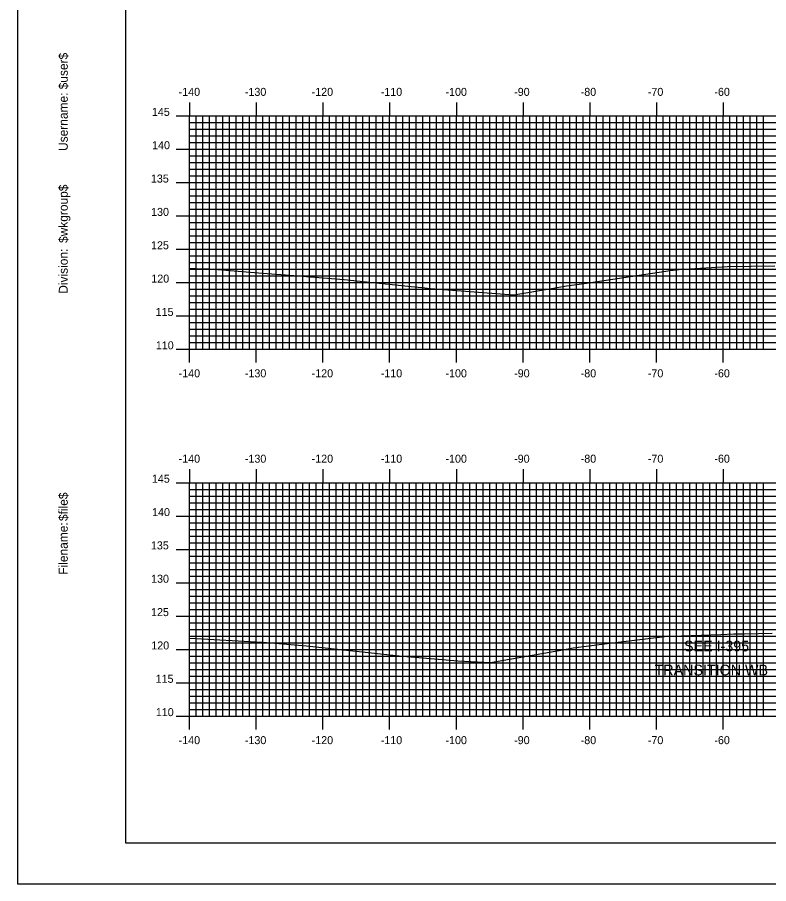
# Model space of a CAD drawing. Extents: x 853328 to 853671, y 364661 to 364881.
# Drawn here: x 853327.5 to 853440.1, y 364661.3 to 364791.1 of the extents above; entities that cross this region are included whole.
import ezdxf

# ---------------------------------------------------------------- set-up
doc = ezdxf.new("R2010")
doc.units = 0
for name, color, linetype in [('ANNOTATION', 7, 'Continuous'), ('BORDER', 7, 'Continuous'), ('H_V ANNOTATION', 7, 'Continuous'), ('MAJOR', 7, 'Continuous'), ('MINOR', 7, 'Continuous'), ('PLOT BOUNDARY', 7, 'Continuous'), ('S_Roadway_Centerline', 7, 'Continuous')]:
    doc.layers.add(name, color=color, linetype=linetype)

msp = doc.modelspace()

# ---------------------------------------------------------------- linework, layer by layer
at = {"layer": 'BORDER'}
msp.add_lwpolyline([(853343.69, 364667.37), (853663.69, 364667.37), (853663.69, 364877.37), (853343.69, 364877.37)], close=True, dxfattribs=at)
at = {"layer": 'MAJOR'}
for p, q in [((853353.29, 364778.38), (853353.29, 364776.37)), ((853363.29, 364778.38), (853363.29, 364776.37)), ((853373.29, 364778.38), (853373.29, 364776.37)), ((853383.29, 364778.38), (853383.29, 364776.37)), ((853393.29, 364778.38), (853393.29, 364776.37)), ((853403.29, 364778.38), (853403.29, 364776.37)), ((853413.29, 364778.38), (853413.29, 364776.37)), ((853423.29, 364778.38), (853423.29, 364776.37)), ((853433.29, 364778.38), (853433.29, 364776.37)), ((853351.29, 364776.37), (853353.29, 364776.37)), ((853353.29, 364776.37), (853633.29, 364776.37)), ((853353.29, 364741.37), (853353.29, 364776.37)), ((853353.29, 364741.37), (853353.29, 364776.37)), ((853353.29, 364776.37), (853633.29, 364776.37)), ((853363.29, 364741.37), (853363.29, 364776.37)), ((853373.29, 364741.37), (853373.29, 364776.37)), ((853383.29, 364741.37), (853383.29, 364776.37)), ((853393.29, 364741.37), (853393.29, 364776.37)), ((853403.29, 364741.37), (853403.29, 364776.37)), ((853413.29, 364741.37), (853413.29, 364776.37)), ((853423.29, 364741.37), (853423.29, 364776.37)), ((853433.29, 364741.37), (853433.29, 364776.37)), ((853351.29, 364771.37), (853353.29, 364771.37)), ((853353.29, 364771.37), (853633.29, 364771.37)), ((853351.29, 364766.37), (853353.29, 364766.37)), ((853353.29, 364766.37), (853633.29, 364766.37)), ((853351.29, 364761.37), (853353.29, 364761.37)), ((853353.29, 364761.37), (853633.29, 364761.37)), ((853351.29, 364756.37), (853353.29, 364756.37)), ((853353.29, 364756.37), (853633.29, 364756.37)), ((853351.29, 364751.37), (853353.29, 364751.37)), ((853353.29, 364751.37), (853633.29, 364751.37)), ((853351.29, 364746.37), (853353.29, 364746.37)), ((853353.29, 364746.37), (853633.29, 364746.37)), ((853351.29, 364741.37), (853353.29, 364741.37)), ((853353.29, 364741.37), (853633.29, 364741.37)), ((853353.29, 364741.37), (853633.29, 364741.37)), ((853353.29, 364739.37), (853353.29, 364741.37)), ((853363.29, 364739.37), (853363.29, 364741.37)), ((853373.29, 364739.37), (853373.29, 364741.37)), ((853383.29, 364739.37), (853383.29, 364741.37)), ((853393.29, 364739.37), (853393.29, 364741.37)), ((853403.29, 364739.37), (853403.29, 364741.37)), ((853413.29, 364739.37), (853413.29, 364741.37)), ((853423.29, 364739.37), (853423.29, 364741.37)), ((853433.29, 364739.37), (853433.29, 364741.37)), ((853353.29, 364723.38), (853353.29, 364721.37)), ((853363.29, 364723.38), (853363.29, 364721.37)), ((853373.29, 364723.38), (853373.29, 364721.37)), ((853383.29, 364723.38), (853383.29, 364721.37)), ((853393.29, 364723.38), (853393.29, 364721.37)), ((853403.29, 364723.38), (853403.29, 364721.37)), ((853413.29, 364723.38), (853413.29, 364721.37)), ((853423.29, 364723.38), (853423.29, 364721.37)), ((853433.29, 364723.38), (853433.29, 364721.37)), ((853351.29, 364721.37), (853353.29, 364721.37)), ((853353.29, 364721.37), (853633.29, 364721.37)), ((853353.29, 364686.37), (853353.29, 364721.37)), ((853353.29, 364686.37), (853353.29, 364721.37)), ((853353.29, 364721.37), (853633.29, 364721.37)), ((853363.29, 364686.37), (853363.29, 364721.37)), ((853373.29, 364686.37), (853373.29, 364721.37)), ((853383.29, 364686.37), (853383.29, 364721.37)), ((853393.29, 364686.37), (853393.29, 364721.37)), ((853403.29, 364686.37), (853403.29, 364721.37)), ((853413.29, 364686.37), (853413.29, 364721.37)), ((853423.29, 364686.37), (853423.29, 364721.37)), ((853433.29, 364686.37), (853433.29, 364721.37)), ((853351.29, 364716.37), (853353.29, 364716.37)), ((853353.29, 364716.37), (853633.29, 364716.37)), ((853351.29, 364711.37), (853353.29, 364711.37)), ((853353.29, 364711.37), (853633.29, 364711.37)), ((853351.29, 364706.37), (853353.29, 364706.37)), ((853353.29, 364706.37), (853633.29, 364706.37)), ((853351.29, 364701.37), (853353.29, 364701.37)), ((853353.29, 364701.37), (853633.29, 364701.37)), ((853351.29, 364696.37), (853353.29, 364696.37)), ((853353.29, 364696.37), (853633.29, 364696.37)), ((853351.29, 364691.37), (853353.29, 364691.37)), ((853353.29, 364691.37), (853633.29, 364691.37)), ((853351.29, 364686.37), (853353.29, 364686.37)), ((853353.29, 364686.37), (853633.29, 364686.37)), ((853353.29, 364686.37), (853633.29, 364686.37)), ((853353.29, 364684.37), (853353.29, 364686.37)), ((853363.29, 364684.37), (853363.29, 364686.37)), ((853373.29, 364684.37), (853373.29, 364686.37)), ((853383.29, 364684.37), (853383.29, 364686.37)), ((853393.29, 364684.37), (853393.29, 364686.37)), ((853403.29, 364684.37), (853403.29, 364686.37)), ((853413.29, 364684.37), (853413.29, 364686.37)), ((853423.29, 364684.37), (853423.29, 364686.37)), ((853433.29, 364684.37), (853433.29, 364686.37))]:
    msp.add_line(p, q, dxfattribs=at)
at = {"layer": 'MINOR'}
for p, q in [((853354.29, 364741.37), (853354.29, 364776.37)), ((853355.29, 364741.37), (853355.29, 364776.37)), ((853356.29, 364741.37), (853356.29, 364776.37)), ((853357.29, 364741.37), (853357.29, 364776.37)), ((853358.29, 364741.37), (853358.29, 364776.37)), ((853359.29, 364741.37), (853359.29, 364776.37)), ((853360.29, 364741.37), (853360.29, 364776.37)), ((853361.29, 364741.37), (853361.29, 364776.37)), ((853362.29, 364741.37), (853362.29, 364776.37)), ((853364.29, 364741.37), (853364.29, 364776.37)), ((853365.29, 364741.37), (853365.29, 364776.37)), ((853366.29, 364741.37), (853366.29, 364776.37)), ((853367.29, 364741.37), (853367.29, 364776.37)), ((853368.29, 364741.37), (853368.29, 364776.37)), ((853369.29, 364741.37), (853369.29, 364776.37)), ((853370.29, 364741.37), (853370.29, 364776.37)), ((853371.29, 364741.37), (853371.29, 364776.37)), ((853372.29, 364741.37), (853372.29, 364776.37)), ((853374.29, 364741.37), (853374.29, 364776.37)), ((853375.29, 364741.37), (853375.29, 364776.37)), ((853376.29, 364741.37), (853376.29, 364776.37)), ((853377.29, 364741.37), (853377.29, 364776.37)), ((853378.29, 364741.37), (853378.29, 364776.37)), ((853379.29, 364741.37), (853379.29, 364776.37)), ((853380.29, 364741.37), (853380.29, 364776.37)), ((853381.29, 364741.37), (853381.29, 364776.37)), ((853382.29, 364741.37), (853382.29, 364776.37)), ((853384.29, 364741.37), (853384.29, 364776.37)), ((853385.29, 364741.37), (853385.29, 364776.37)), ((853386.29, 364741.37), (853386.29, 364776.37)), ((853387.29, 364741.37), (853387.29, 364776.37)), ((853388.29, 364741.37), (853388.29, 364776.37)), ((853389.29, 364741.37), (853389.29, 364776.37)), ((853390.29, 364741.37), (853390.29, 364776.37)), ((853391.29, 364741.37), (853391.29, 364776.37)), ((853392.29, 364741.37), (853392.29, 364776.37)), ((853394.29, 364741.37), (853394.29, 364776.37)), ((853395.29, 364741.37), (853395.29, 364776.37)), ((853396.29, 364741.37), (853396.29, 364776.37)), ((853397.29, 364741.37), (853397.29, 364776.37)), ((853398.29, 364741.37), (853398.29, 364776.37)), ((853399.29, 364741.37), (853399.29, 364776.37)), ((853400.29, 364741.37), (853400.29, 364776.37)), ((853401.29, 364741.37), (853401.29, 364776.37)), ((853402.29, 364741.37), (853402.29, 364776.37)), ((853404.29, 364741.37), (853404.29, 364776.37)), ((853405.29, 364741.37), (853405.29, 364776.37)), ((853406.29, 364741.37), (853406.29, 364776.37)), ((853407.29, 364741.37), (853407.29, 364776.37)), ((853408.29, 364741.37), (853408.29, 364776.37)), ((853409.29, 364741.37), (853409.29, 364776.37)), ((853410.29, 364741.37), (853410.29, 364776.37)), ((853411.29, 364741.37), (853411.29, 364776.37)), ((853412.29, 364741.37), (853412.29, 364776.37)), ((853414.29, 364741.37), (853414.29, 364776.37)), ((853415.29, 364741.37), (853415.29, 364776.37)), ((853416.29, 364741.37), (853416.29, 364776.37)), ((853417.29, 364741.37), (853417.29, 364776.37)), ((853418.29, 364741.37), (853418.29, 364776.37)), ((853419.29, 364741.37), (853419.29, 364776.37)), ((853420.29, 364741.37), (853420.29, 364776.37)), ((853421.29, 364741.37), (853421.29, 364776.37)), ((853422.29, 364741.37), (853422.29, 364776.37)), ((853424.29, 364741.37), (853424.29, 364776.37)), ((853425.29, 364741.37), (853425.29, 364776.37)), ((853426.29, 364741.37), (853426.29, 364776.37)), ((853427.29, 364741.37), (853427.29, 364776.37)), ((853428.29, 364741.37), (853428.29, 364776.37)), ((853429.29, 364741.37), (853429.29, 364776.37)), ((853430.29, 364741.37), (853430.29, 364776.37)), ((853431.29, 364741.37), (853431.29, 364776.37)), ((853432.29, 364741.37), (853432.29, 364776.37)), ((853434.29, 364741.37), (853434.29, 364776.37)), ((853435.29, 364741.37), (853435.29, 364776.37)), ((853436.29, 364741.37), (853436.29, 364776.37)), ((853437.29, 364741.37), (853437.29, 364776.37)), ((853438.29, 364741.37), (853438.29, 364776.37)), ((853439.29, 364741.37), (853439.29, 364776.37)), ((853353.29, 364775.37), (853633.29, 364775.37)), ((853353.29, 364775.37), (853355.3, 364775.37)), ((853353.29, 364774.37), (853633.29, 364774.37)), ((853353.29, 364774.37), (853355.3, 364774.37)), ((853353.29, 364773.37), (853633.29, 364773.37)), ((853353.29, 364773.37), (853355.3, 364773.37)), ((853353.29, 364772.37), (853633.29, 364772.37)), ((853353.29, 364772.37), (853355.3, 364772.37)), ((853353.29, 364770.37), (853633.29, 364770.37)), ((853353.29, 364770.37), (853355.3, 364770.37)), ((853353.29, 364769.37), (853633.29, 364769.37)), ((853353.29, 364769.37), (853355.3, 364769.37)), ((853353.29, 364768.37), (853633.29, 364768.37)), ((853353.29, 364768.37), (853355.3, 364768.37)), ((853353.29, 364767.37), (853633.29, 364767.37)), ((853353.29, 364767.37), (853355.3, 364767.37)), ((853353.29, 364765.37), (853633.29, 364765.37)), ((853353.29, 364765.37), (853355.3, 364765.37)), ((853353.29, 364764.37), (853633.29, 364764.37)), ((853353.29, 364764.37), (853355.3, 364764.37)), ((853353.29, 364763.37), (853633.29, 364763.37)), ((853353.29, 364763.37), (853355.3, 364763.37)), ((853353.29, 364762.37), (853633.29, 364762.37)), ((853353.29, 364762.37), (853355.3, 364762.37)), ((853353.29, 364760.37), (853633.29, 364760.37)), ((853353.29, 364760.37), (853355.3, 364760.37)), ((853353.29, 364759.37), (853633.29, 364759.37)), ((853353.29, 364759.37), (853355.3, 364759.37)), ((853353.29, 364758.37), (853633.29, 364758.37)), ((853353.29, 364758.37), (853355.3, 364758.37)), ((853353.29, 364757.37), (853633.29, 364757.37)), ((853353.29, 364757.37), (853355.3, 364757.37)), ((853353.29, 364755.37), (853633.29, 364755.37)), ((853353.29, 364755.37), (853355.3, 364755.37)), ((853353.29, 364754.37), (853633.29, 364754.37)), ((853353.29, 364754.37), (853355.3, 364754.37)), ((853353.29, 364753.37), (853633.29, 364753.37)), ((853353.29, 364753.37), (853355.3, 364753.37)), ((853353.29, 364752.37), (853633.29, 364752.37)), ((853353.29, 364752.37), (853355.3, 364752.37)), ((853353.29, 364750.37), (853633.29, 364750.37)), ((853353.29, 364750.37), (853355.3, 364750.37)), ((853353.29, 364749.37), (853633.29, 364749.37)), ((853353.29, 364749.37), (853355.3, 364749.37)), ((853353.29, 364748.37), (853633.29, 364748.37)), ((853353.29, 364748.37), (853355.3, 364748.37)), ((853353.29, 364747.37), (853633.29, 364747.37)), ((853353.29, 364747.37), (853355.3, 364747.37)), ((853353.29, 364745.37), (853633.29, 364745.37)), ((853353.29, 364745.37), (853355.3, 364745.37)), ((853353.29, 364744.37), (853633.29, 364744.37)), ((853353.29, 364744.37), (853355.3, 364744.37)), ((853353.29, 364743.37), (853633.29, 364743.37)), ((853353.29, 364743.37), (853355.3, 364743.37)), ((853353.29, 364742.37), (853633.29, 364742.37)), ((853353.29, 364742.37), (853355.3, 364742.37)), ((853354.29, 364686.37), (853354.29, 364721.37)), ((853355.29, 364686.37), (853355.29, 364721.37)), ((853356.29, 364686.37), (853356.29, 364721.37)), ((853357.29, 364686.37), (853357.29, 364721.37)), ((853358.29, 364686.37), (853358.29, 364721.37)), ((853359.29, 364686.37), (853359.29, 364721.37)), ((853360.29, 364686.37), (853360.29, 364721.37)), ((853361.29, 364686.37), (853361.29, 364721.37)), ((853362.29, 364686.37), (853362.29, 364721.37)), ((853364.29, 364686.37), (853364.29, 364721.37)), ((853365.29, 364686.37), (853365.29, 364721.37)), ((853366.29, 364686.37), (853366.29, 364721.37)), ((853367.29, 364686.37), (853367.29, 364721.37)), ((853368.29, 364686.37), (853368.29, 364721.37)), ((853369.29, 364686.37), (853369.29, 364721.37)), ((853370.29, 364686.37), (853370.29, 364721.37)), ((853371.29, 364686.37), (853371.29, 364721.37)), ((853372.29, 364686.37), (853372.29, 364721.37)), ((853374.29, 364686.37), (853374.29, 364721.37)), ((853375.29, 364686.37), (853375.29, 364721.37)), ((853376.29, 364686.37), (853376.29, 364721.37)), ((853377.29, 364686.37), (853377.29, 364721.37)), ((853378.29, 364686.37), (853378.29, 364721.37)), ((853379.29, 364686.37), (853379.29, 364721.37)), ((853380.29, 364686.37), (853380.29, 364721.37)), ((853381.29, 364686.37), (853381.29, 364721.37)), ((853382.29, 364686.37), (853382.29, 364721.37)), ((853384.29, 364686.37), (853384.29, 364721.37)), ((853385.29, 364686.37), (853385.29, 364721.37)), ((853386.29, 364686.37), (853386.29, 364721.37)), ((853387.29, 364686.37), (853387.29, 364721.37)), ((853388.29, 364686.37), (853388.29, 364721.37)), ((853389.29, 364686.37), (853389.29, 364721.37)), ((853390.29, 364686.37), (853390.29, 364721.37)), ((853391.29, 364686.37), (853391.29, 364721.37)), ((853392.29, 364686.37), (853392.29, 364721.37)), ((853394.29, 364686.37), (853394.29, 364721.37)), ((853395.29, 364686.37), (853395.29, 364721.37)), ((853396.29, 364686.37), (853396.29, 364721.37)), ((853397.29, 364686.37), (853397.29, 364721.37)), ((853398.29, 364686.37), (853398.29, 364721.37)), ((853399.29, 364686.37), (853399.29, 364721.37)), ((853400.29, 364686.37), (853400.29, 364721.37)), ((853401.29, 364686.37), (853401.29, 364721.37)), ((853402.29, 364686.37), (853402.29, 364721.37)), ((853404.29, 364686.37), (853404.29, 364721.37)), ((853405.29, 364686.37), (853405.29, 364721.37)), ((853406.29, 364686.37), (853406.29, 364721.37)), ((853407.29, 364686.37), (853407.29, 364721.37)), ((853408.29, 364686.37), (853408.29, 364721.37)), ((853409.29, 364686.37), (853409.29, 364721.37)), ((853410.29, 364686.37), (853410.29, 364721.37)), ((853411.29, 364686.37), (853411.29, 364721.37)), ((853412.29, 364686.37), (853412.29, 364721.37)), ((853414.29, 364686.37), (853414.29, 364721.37)), ((853415.29, 364686.37), (853415.29, 364721.37)), ((853416.29, 364686.37), (853416.29, 364721.37)), ((853417.29, 364686.37), (853417.29, 364721.37)), ((853418.29, 364686.37), (853418.29, 364721.37)), ((853419.29, 364686.37), (853419.29, 364721.37)), ((853420.29, 364686.37), (853420.29, 364721.37)), ((853421.29, 364686.37), (853421.29, 364721.37)), ((853422.29, 364686.37), (853422.29, 364721.37)), ((853424.29, 364686.37), (853424.29, 364721.37)), ((853425.29, 364686.37), (853425.29, 364721.37)), ((853426.29, 364686.37), (853426.29, 364721.37)), ((853427.29, 364686.37), (853427.29, 364721.37)), ((853428.29, 364686.37), (853428.29, 364721.37)), ((853429.29, 364686.37), (853429.29, 364721.37)), ((853430.29, 364686.37), (853430.29, 364721.37)), ((853431.29, 364686.37), (853431.29, 364721.37)), ((853432.29, 364686.37), (853432.29, 364721.37)), ((853434.29, 364686.37), (853434.29, 364721.37)), ((853435.29, 364686.37), (853435.29, 364721.37)), ((853436.29, 364686.37), (853436.29, 364721.37)), ((853437.29, 364686.37), (853437.29, 364721.37)), ((853438.29, 364686.37), (853438.29, 364721.37)), ((853439.29, 364686.37), (853439.29, 364721.37)), ((853353.29, 364720.37), (853633.29, 364720.37)), ((853353.29, 364720.37), (853355.3, 364720.37)), ((853353.29, 364719.37), (853633.29, 364719.37)), ((853353.29, 364719.37), (853355.3, 364719.37)), ((853353.29, 364718.37), (853633.29, 364718.37)), ((853353.29, 364718.37), (853355.3, 364718.37)), ((853353.29, 364717.37), (853633.29, 364717.37)), ((853353.29, 364717.37), (853355.3, 364717.37)), ((853353.29, 364715.37), (853633.29, 364715.37)), ((853353.29, 364715.37), (853355.3, 364715.37)), ((853353.29, 364714.37), (853633.29, 364714.37)), ((853353.29, 364714.37), (853355.3, 364714.37)), ((853353.29, 364713.37), (853633.29, 364713.37)), ((853353.29, 364713.37), (853355.3, 364713.37)), ((853353.29, 364712.37), (853633.29, 364712.37)), ((853353.29, 364712.37), (853355.3, 364712.37)), ((853353.29, 364710.37), (853633.29, 364710.37)), ((853353.29, 364710.37), (853355.3, 364710.37)), ((853353.29, 364709.37), (853633.29, 364709.37)), ((853353.29, 364709.37), (853355.3, 364709.37)), ((853353.29, 364708.37), (853633.29, 364708.37)), ((853353.29, 364708.37), (853355.3, 364708.37)), ((853353.29, 364707.37), (853633.29, 364707.37)), ((853353.29, 364707.37), (853355.3, 364707.37)), ((853353.29, 364705.37), (853633.29, 364705.37)), ((853353.29, 364705.37), (853355.3, 364705.37)), ((853353.29, 364704.37), (853633.29, 364704.37)), ((853353.29, 364704.37), (853355.3, 364704.37)), ((853353.29, 364703.37), (853633.29, 364703.37)), ((853353.29, 364703.37), (853355.3, 364703.37)), ((853353.29, 364702.37), (853633.29, 364702.37)), ((853353.29, 364702.37), (853355.3, 364702.37)), ((853353.29, 364700.37), (853633.29, 364700.37)), ((853353.29, 364700.37), (853355.3, 364700.37)), ((853353.29, 364699.37), (853633.29, 364699.37)), ((853353.29, 364699.37), (853355.3, 364699.37)), ((853353.29, 364698.37), (853633.29, 364698.37)), ((853353.29, 364698.37), (853355.3, 364698.37)), ((853353.29, 364697.37), (853633.29, 364697.37)), ((853353.29, 364697.37), (853355.3, 364697.37)), ((853353.29, 364695.37), (853633.29, 364695.37)), ((853353.29, 364695.37), (853355.3, 364695.37)), ((853353.29, 364694.37), (853633.29, 364694.37)), ((853353.29, 364694.37), (853355.3, 364694.37)), ((853353.29, 364693.37), (853633.29, 364693.37)), ((853353.29, 364693.37), (853355.3, 364693.37)), ((853353.29, 364692.37), (853633.29, 364692.37)), ((853353.29, 364692.37), (853355.3, 364692.37)), ((853353.29, 364690.37), (853633.29, 364690.37)), ((853353.29, 364690.37), (853355.3, 364690.37)), ((853353.29, 364689.37), (853633.29, 364689.37)), ((853353.29, 364689.37), (853355.3, 364689.37)), ((853353.29, 364688.37), (853633.29, 364688.37)), ((853353.29, 364688.37), (853355.3, 364688.37)), ((853353.29, 364687.37), (853633.29, 364687.37)), ((853353.29, 364687.37), (853355.3, 364687.37))]:
    msp.add_line(p, q, dxfattribs=at)
at = {"layer": 'PLOT BOUNDARY'}
msp.add_lwpolyline([(853327.51, 364661.25), (853667.51, 364661.25), (853667.51, 364881.25), (853327.51, 364881.25)], close=True, dxfattribs=at)
at = {"layer": 'S_Roadway_Centerline'}
for points in [[(853353.29, 364753.52), (853354.2, 364753.5), (853356.18, 364753.45), (853356.94, 364753.4), (853364.24, 364752.77), (853367.04, 364752.57), (853376.48, 364751.83), (853386.51, 364750.8), (853388.12, 364750.63), (853389.39, 364750.5), (853401.2, 364749.59), (853401.88, 364749.56), (853407.56, 364750.51), (853409.8, 364750.89), (853410.53, 364750.99), (853412.42, 364751.25), (853425.32, 364753.2), (853427.12, 364753.4), (853427.35, 364753.41), (853431.54, 364753.65), (853433.91, 364753.78), (853441.02, 364753.88)], [(853353.29, 364698.08), (853364.25, 364697.46), (853366.07, 364697.31), (853370.85, 364696.89), (853384.71, 364695.43), (853393.52, 364694.67), (853398.39, 364694.4), (853398.4, 364694.39), (853409.22, 364696.33), (853410.81, 364696.59), (853415.49, 364697.22), (853422.42, 364698.05), (853424.49, 364698.3), (853425.53, 364698.35), (853432.91, 364698.6), (853434.86, 364698.7), (853436.47, 364698.72), (853440.63, 364698.82)]]:
    msp.add_lwpolyline(points, dxfattribs=at)

# ---------------------------------------------------------------- texts
at = {"layer": 'ANNOTATION'}
for s, p in [('SEE I-395 ', (853427.4, 364696.08)), ('TRANSITION WB', (853422.99, 364692.48))]:
    msp.add_text(s, height=1.6, dxfattribs=at).set_placement(p)
at = {"layer": 'BORDER'}
for s, p in [('$user$', (853335.06, 364780.35)), ('Username:', (853335.06, 364771.11)), ('$wkgroup$', (853335.06, 364757.31)), ('Division:', (853335.06, 364749.7)), ('$file$', (853335.06, 364715.62)), ('Filename:', (853335.06, 364707.57))]:
    msp.add_text(s, height=1.339, rotation=90, dxfattribs=at).set_placement(p)
at = {"layer": 'H_V ANNOTATION'}
for s, p in [('-140', (853351.68, 364779.37)), ('-130', (853361.6, 364779.37)), ('-120', (853371.61, 364779.37)), ('-110', (853381.96, 364779.37)), ('-100', (853391.66, 364779.37)), ('-90', (853401.95, 364779.37)), ('-80', (853411.92, 364779.37)), ('-70', (853421.98, 364779.37)), ('-60', (853431.95, 364779.37)), ('145', (853347.67, 364776.37)), ('140', (853347.7, 364771.37)), ('135', (853347.52, 364766.37)), ('130', (853347.55, 364761.37)), ('125', (853347.54, 364756.37)), ('120', (853347.58, 364751.37)), ('115', (853348.23, 364746.37)), ('110', (853348.26, 364741.37)), ('-140', (853351.68, 364737.17)), ('-130', (853361.6, 364737.17)), ('-120', (853371.61, 364737.17)), ('-110', (853381.96, 364737.17)), ('-100', (853391.66, 364737.17)), ('-90', (853401.95, 364737.17)), ('-80', (853411.92, 364737.17)), ('-70', (853421.98, 364737.17)), ('-60', (853431.95, 364737.17)), ('-140', (853351.68, 364724.37)), ('-130', (853361.6, 364724.37)), ('-120', (853371.61, 364724.37)), ('-110', (853381.96, 364724.37)), ('-100', (853391.66, 364724.37)), ('-90', (853401.95, 364724.37)), ('-80', (853411.92, 364724.37)), ('-70', (853421.98, 364724.37)), ('-60', (853431.95, 364724.37)), ('145', (853347.67, 364721.37)), ('140', (853347.7, 364716.37)), ('135', (853347.52, 364711.37)), ('130', (853347.55, 364706.37)), ('125', (853347.54, 364701.37)), ('120', (853347.58, 364696.37)), ('115', (853348.23, 364691.37)), ('110', (853348.26, 364686.37)), ('-140', (853351.68, 364682.17)), ('-130', (853361.6, 364682.17)), ('-120', (853371.61, 364682.17)), ('-110', (853381.96, 364682.17)), ('-100', (853391.66, 364682.17)), ('-90', (853401.95, 364682.17)), ('-80', (853411.92, 364682.17)), ('-70', (853421.98, 364682.17)), ('-60', (853431.95, 364682.17))]:
    msp.add_text(s, height=1.2, dxfattribs=at).set_placement(p)
at = {"layer": 'MAJOR'}
for p in [(853353.29, 364741.37), (853353.29, 364686.37)]:
    msp.add_text('-', height=0.012, dxfattribs=at).set_placement(p)

doc.saveas('drawing.dxf')
